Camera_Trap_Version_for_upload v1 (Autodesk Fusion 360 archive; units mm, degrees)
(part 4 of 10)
sketch "Sketch1" plane through (-17, 0, 0) normal (-1, 0, 0) x axis (0, -1, 0)
  line L1 (0, 133.1) -> (0, 122)
  line L2 (0, 70.6) -> (0, 133.1)
  line L3 (0, 143.2) -> (0, 154.3)
  line L4 (0, 143.2) -> (0, 205)
  line L5 (10, 225) -> (-10, 225)
  line L6 (20, 60) -> (20, 215)
  line L7 (-20, 50) -> (10, 50)
  line L8 (-20, 215) -> (-20, 50)
  line L9 (12.5837, 115) -> (-10, 115)
  line L10 (12.5837, 90.729) -> (12.5837, 115)
  line L11 (-10, 90.729) -> (12.5837, 90.729)
  line L12 (-10, 115) -> (-10, 90.729)
  line L13 (10, 185) -> (-10, 185)
  line L14 (10, 160) -> (10, 185)
  line L15 (-10, 160) -> (10, 160)
  line L16 (-10, 185) -> (-10, 160)
  circle C1 centre (0, 70.6) radius 13.1
  circle C2 centre (0, 70.6) radius 11.1
  circle C3 centre (0, 133.1) radius 11.1
  circle C4 centre (0, 143.2) radius 11.1
  arc A1 centre (-10, 215) radius 10 clockwise from (-20, 215) to (-10, 225)
  arc A2 centre (10, 215) radius 10 clockwise from (10, 225) to (20, 215)
  arc A3 centre (10, 60) radius 10 clockwise from (20, 60) to (10, 50)
  point P5 (0, 133.1)
  point P6 (0, 133.1)
  point P7 (0, 133.1)
  point P3 (0, 70.6)
  point P8 (0, 70.6)
  point P10 (0, 143.2)
  point P11 (0, 143.2)
  point P13 (0, 143.2)
  point P4 (0, 122)
  point P9 (0, 154.3)
  concentric C1 C2
  vertical L1
  coincident P5 P6
  coincident P6 P7
  coincident P3 P8
  parallel L1 L2
  vertical L3
  coincident P10 P11
  coincident P11 P13
  parallel L3 L4
  horizontal L5
  vertical L6
  horizontal L7
  vertical L8
  horizontal L9
  vertical L10
  horizontal L11
  vertical L12
  horizontal L13
  vertical L14
  horizontal L15
  vertical L16
  tangent L8 A1
  tangent L5 A1
  tangent L5 A2
  tangent L6 A2
  equal A1 A2
  tangent L6 A3
  tangent L7 A3
  equal A1 A3
  dimension "d792" diameter C2 = 22.2
  dimension "d793" distance P4 P5 = 11.1
  dimension "d794" diameter C3 = 22.2
  dimension "d796" distance P9 P10 = 11.1
  dimension "d797" diameter C4 = 22.2
  dimension "d798" radius A1 = 10
extrude "Extrude1" new body sketch "Sketch1" profile of C1 L5 L6 L7 L8 L9 L10 L11 L12 L13 L14 L15 L16 A1 A2 A3 against normal blind 5
combine "Combine1"
extrude "Extrude8" new body sketch "Sketch1" profile of L6 L7 L10 L11 L21 L22 L24 L25 L26 L27 against normal blind 149 and along normal blind 7 bodies "Back_wall"
sketch "Sketch2" plane through (0, 0, 100) normal (0, 0, 1) x axis (-1, 0, 0)
  line L1 (-136, 15) -> (-136, -15)
  line L2 (-139, 15) -> (-136, 15)
  line L3 (-139, -15) -> (-139, 15)
  line L4 (-136, -15) -> (-139, -15)
combine "Combine3"
copy_paste_bodies "CopyPasteBodies2"
move "Move2"
extrude "Extrude7" add of existing geometry blind 1
extrude "Extrude8" new body of existing geometry blind 12
extrude "Extrude9" new body of existing geometry blind 10
extrude "Extrude10" new body of existing geometry blind 52.5
extrude "Extrude11" new body of existing geometry blind 51
sketch "Sketch4" plane through (0, 0, 180.1585) normal (0, 0, 1) x axis (-1, 0, 0)
  line L1 (-39.225, -41) -> (-39.225, -35)
  line L2 (11.775, -41) -> (-39.225, -41)
  line L3 (11.775, -35) -> (11.775, -41)
  line L4 (-39.225, -35) -> (11.775, -35)
  line L5 (1.775, -41) -> (11.775, -41)
  line L6 (1.775, -31) -> (1.775, -41)
  line L7 (11.775, -31) -> (1.775, -31)
  line L8 (11.775, -41) -> (11.775, -31)
  point P4 (11.775, -41)
  point P6 (11.775, -41)
  point P7 (1.775, -41)
  point P9 (11.775, -31)
  horizontal L5
  vertical L6
  horizontal L7
  vertical L8
  coincident P4 P6
  dimension "d822" distance P6 P7 = 10
  dimension "d823" distance P6 P9 = 10
extrude "Extrude12" new body sketch "Sketch4" profile of L2 L3 L4 L5 L6 L8 along normal blind 30
sketch "Sketch5" plane through (-20.1975, 0, 0) normal (-1, 0, 0) x axis (0, -1, 0)
  line L1 (-52.3693, 30.245) -> (-52.3693, 255.1758)
  line L2 (-32.3693, 30.245) -> (-52.3693, 30.245)
  line L3 (-2.1894, 30.245) -> (-32.3693, 30.245)
  curve K1 (36.0257, 253.4503) -> (39.9781, 236.096)
  line L4 (3.2602, 255.1758) -> (36.0257, 253.4503)
  line L5 (-52.3693, 255.1758) -> (-1.9988, 255.1758)
  line L6 (-42, 182.1437) -> (-42, 210)
  arc A1 centre (-2.1894, 80.245) radius 50 clockwise from (40.2825, 106.6295) to (-2.1894, 30.245)
  arc A2 centre (82.7543, 133.0139) radius 50 clockwise from (40.2825, 106.6295) to (32.7706, 134.2915)
  arc A3 centre (2.3992, 135.0677) radius 30.3814 clockwise from (32.4457, 139.5658) to (32.7706, 134.2915)
  arc A4 centre (81.8947, 146.9684) radius 50 clockwise from (32.4457, 139.5658) to (41.2627, 176.1067)
  arc A5 centre (0.6307, 205.245) radius 50 clockwise from (39.9781, 236.096) to (41.2627, 176.1067)
  arc A6 centre (0.6307, 205.245) radius 50 clockwise from (-1.9988, 255.1758) to (3.2602, 255.1758)
  vertical L6
sketch "Sketch6" plane through (0, 35, 0) normal (0, -1, 0) x axis (1, 0, 0)
  line L1 (-1.775, 180.1585) -> (-11.775, 180.1585)
  line L2 (-1.775, 210.1585) -> (-1.775, 180.1585)
  line L3 (-11.775, 210.1585) -> (-1.775, 210.1585)
  line L4 (-11.775, 180.1585) -> (-11.775, 210.1585)
  line L5 (-20.2, 195.1585) -> (-11.775, 195.1585)
  line L6 (-11.775, 205) -> (-20.2, 205)
  line L7 (-11.775, 195.1585) -> (-11.775, 205)
  line L8 (-26, 205) -> (-20.2, 205)
  line L9 (-26, 195.1585) -> (-20.2, 195.1585)
  line L10 (-26, 205) -> (-26, 195.1585)
  point P6 (-11.775, 195.1585)
  horizontal L5
  horizontal L6
  vertical L7
  midpoint L4 P6
  parallel L6 L8
  parallel L5 L9
  perpendicular L8 L10
extrude "Extrude13" new body sketch "Sketch6" profile of L4 L5 L6 L7 against normal blind 6
sketch "Sketch7" plane through (0, 52.3693, 0) normal (0, -1, 0) x axis (1, 0, 0)
  line L1 (135.8025, 30.245) -> (-20.1975, 30.245)
  line L2 (135.8025, 292.8982) -> (135.8025, 30.245)
  line L3 (-20.1975, 292.8982) -> (135.8025, 292.8982)
  line L4 (-20.1975, 30.245) -> (-20.1975, 292.8982)
  line L5 (8.4868, 210) -> (0, 210)
  line L6 (8.4868, 184.467) -> (8.4868, 210)
  line L7 (0, 184.467) -> (8.4868, 184.467)
  line L8 (0, 210) -> (0, 184.467)
  line L9 (4.2434, 184.467) -> (4.2434, 210)
  circle C1 centre (4.2434, 204.9529) radius 1.5
  circle C2 centre (4.2434, 190.0169) radius 1.5
  point P10 (4.2434, 210)
  point P11 (4.2434, 184.467)
  point P12 (4.2434, 204.9529)
  point P13 (4.2434, 190.0169)
  horizontal L5
  vertical L6
  horizontal L7
  vertical L8
  midpoint L5 P10
  midpoint L7 P11
  coincident L9 P12
  coincident L9 P13
  dimension "d830" diameter C1 = 3
  dimension "d831" diameter C2 = 3
extrude "Extrude15" new body sketch "Sketch7" profile of L5 L6 L7 L8 C1 C2 along normal blind 25
sketch "Sketch8" plane through (0, 0, 0) normal (-1, 0, 0) x axis (0, -1, 0)
  line L1 (-52.3693, 184.467) -> (-52.3693, 210)
  line L2 (-27.3693, 184.467) -> (-52.3693, 184.467)
  line L3 (-27.3693, 210) -> (-27.3693, 184.467)
  line L4 (-52.3693, 210) -> (-27.3693, 210)
  line L5 (-27.3693, 210) -> (-33, 210)
  line L6 (-27.3693, 184.467) -> (-27.3693, 210)
  line L7 (-33, 184.467) -> (-27.3693, 184.467)
  line L8 (-33, 210) -> (-33, 184.467)
  point P4 (-27.3693, 184.467)
  point P8 (-27.3693, 184.467)
  point P6 (-33, 210)
  horizontal L5
  vertical L6
  horizontal L7
  vertical L8
  coincident P4 P8
  coincident L4 P6
sketch "Sketch9" plane through (0, 0, 0) normal (-1, 0, 0) x axis (0, -1, 0)
  line L1 (-52.3693, 184.467) -> (-52.3693, 210)
  line L2 (-27.3693, 184.467) -> (-52.3693, 184.467)
  line L3 (-27.3693, 210) -> (-27.3693, 184.467)
  line L4 (-52.3693, 210) -> (-27.3693, 210)
extrude "Extrude16" add sketch "Sketch8" profile of L2 L3 L4 L5 L6 L7 L8 along normal blind 14
sketch "Sketch4" plane through (-17, 0, 0) normal (1, 0, 0) x axis (0, 1, 0)
  line L1 (53, 254.9308) -> (53, 30)
  line L2 (2.6295, 254.9308) -> (53, 254.9308)
  line L3 (-35.395, 253.2053) -> (-2.6295, 254.9308)
  curve K1 (-35.395, 253.2053) -> (-39.3474, 235.851)
  line L4 (33, 30) -> (2.8201, 30)
  line L5 (53, 30) -> (33, 30)
  line L6 (53, 210) -> (43, 210)
  line L7 (53, 185) -> (53, 210)
  line L8 (43, 185) -> (53, 185)
  line L9 (43, 210) -> (43, 185)
  line L10 (48, 185) -> (43, 185)
  line L11 (48, 210) -> (48, 185)
  line L12 (43, 210) -> (48, 210)
  line L13 (43, 185) -> (43, 210)
  arc A1 centre (0, 205) radius 50 clockwise from (-2.6295, 254.9308) to (2.6295, 254.9308)
  arc A2 centre (0, 205) radius 50 clockwise from (-40.632, 175.8617) to (-39.3474, 235.851)
  arc A3 centre (-81.264, 146.7234) radius 50 clockwise from (-40.632, 175.8617) to (-31.815, 139.3208)
  arc A4 centre (-1.7685, 134.8228) radius 30.3814 clockwise from (-32.1399, 134.0465) to (-31.815, 139.3208)
  arc A5 centre (-82.1236, 132.769) radius 50 clockwise from (-32.1399, 134.0465) to (-39.6517, 106.3845)
  arc A6 centre (2.8201, 80) radius 50 clockwise from (2.8201, 30) to (-39.6517, 106.3845)
  circle C1 centre (51, 205) radius 1.5
  point P21 (53, 185)
  point P25 (48, 210)
  horizontal L6
  vertical L7
  horizontal L8
  vertical L9
  coincident L1 P21
  horizontal L10
  vertical L11
  horizontal L12
  vertical L13
  midpoint L6 P25
  dimension "d836" diameter C1 = 3
extrude "Extrude9" new body sketch "Sketch4" profile of L1 L6 L7 L8 C1 L11 along normal blind 5
extrude "Extrude10" new body sketch "Sketch4" profile of L6 L8 L9 L10 L11 L12 L13 along normal blind 17
sketch "Sketch5" plane through (0, 43, 0) normal (0, -1, 0) x axis (1, 0, 0)
  line L1 (0, 185) -> (-17, 185)
  line L2 (0, 210) -> (0, 185)
  line L3 (-17, 210) -> (0, 210)
  line L4 (0, 210) -> (-5, 210)
  line L5 (0, 185) -> (0, 210)
  line L6 (-5, 185) -> (0, 185)
  line L7 (-5, 210) -> (-5, 185)
  line L8 (-17, 185) -> (-17, 210)
  point P4 (0, 185)
  point P8 (0, 185)
  point P6 (-5, 210)
  horizontal L4
  vertical L5
  horizontal L6
  vertical L7
  coincident P4 P8
  coincident L3 P6
extrude "Extrude11" add sketch "Sketch5" profile of L1 L2 L3 L4 L5 L6 L7 along normal blind 7
sketch "Sketch7" plane through (-24, 0, 0) normal (-1, 0, 0) x axis (0, -1, 0)
  line L1 (-53, 30) -> (-53, 254.9308)
  line L2 (-33, 30) -> (-53, 30)
  line L3 (-2.8201, 30) -> (-33, 30)
  curve K1 (35.395, 253.2053) -> (39.3474, 235.851)
  line L4 (2.6295, 254.9308) -> (35.395, 253.2053)
  line L5 (-53, 254.9308) -> (-2.6295, 254.9308)
  line L6 (-35, 194) -> (-42, 194)
  line L7 (-35, 205) -> (-35, 194)
  line L8 (-35, 213) -> (-35, 205)
  line L9 (-42, 213) -> (-42, 194)
  line L10 (-35, 213) -> (-42, 213)
  arc A1 centre (-2.8201, 80) radius 50 clockwise from (39.6517, 106.3845) to (-2.8201, 30)
  arc A2 centre (82.1236, 132.769) radius 50 clockwise from (39.6517, 106.3845) to (32.1399, 134.0465)
  arc A3 centre (1.7685, 134.8228) radius 30.3814 clockwise from (31.815, 139.3208) to (32.1399, 134.0465)
  arc A4 centre (81.264, 146.7234) radius 50 clockwise from (31.815, 139.3208) to (40.632, 175.8617)
  arc A5 centre (0, 205) radius 50 clockwise from (39.3474, 235.851) to (40.632, 175.8617)
  arc A6 centre (0, 205) radius 50 clockwise from (-2.6295, 254.9308) to (2.6295, 254.9308)
  point P21 (-35, 205)
  point P22 (-35, 213)
  horizontal L6
  perpendicular L6 L7
  perpendicular L6 L8
  perpendicular L6 L9
  dimension "d844" distance P21 P22 = 8
extrude "Extrude13" cut sketch "Sketch7" profile of L6 L7 L8 L9 L10 against normal blind 7
extrude "Extrude14" cut of existing geometry blind -6
extrude "Extrude15" cut of existing geometry blind -4
combine "Combine3"
fillet "Fillet2" radius 10
combine "Combine4"
extrude "Extrude18" add of existing geometry blind 12
fillet "Fillet3" radius 10
fillet "Fillet5" radius 5
fillet "Fillet6" radius 10
fillet "Fillet7" radius 5
fillet "Fillet9" radius 5
fillet "Fillet11" radius 1
extrude "Extrude16" new body sketch "Sketch1" profile of L19 L33 L34 L35 L36 A7 A8 A9 A10 against normal blind 10 bodies "OLD_LL_Tensor_holders"
extrude "Extrude17" new body sketch "Sketch1" profile of L14 L28 L29 L30 L31 A3 A4 A5 A6 against normal blind 10 bodies "OLD_LU_Tensor_holders (1)"
move "Move3"
move "Move4"
sketch "Sketch8" plane through (0, -44, 0) normal (0, -1, 0) x axis (1, 0, 0)
  line L1 (-17, 183) -> (-17, 197)
  line L2 (-7, 183) -> (-17, 183)
  line L3 (-7, 197) -> (-7, 183)
  line L4 (-17, 197) -> (-7, 197)
  line L5 (-12, 193) -> (-17, 193)
  line L6 (-12, 185) -> (-12, 193)
  line L7 (-17, 185) -> (-12, 185)
  line L8 (-17, 193) -> (-17, 185)
  point P6 (-17, 193)
  point P7 (-12, 193)
  point P9 (-17, 185)
  horizontal L5
  vertical L6
  horizontal L7
  vertical L8
  coincident L1 P6
  dimension "d895" distance P6 P7 = 5
  dimension "d896" distance P6 P9 = 8
extrude "Extrude18" cut sketch "Sketch8" profile of L1 L5 L6 L7 L8 against normal blind 10
sketch "Sketch9" plane through (0, -44, 0) normal (0, -1, 0) x axis (1, 0, 0)
  line L1 (-17, 63) -> (-17, 77)
  line L2 (-7, 63) -> (-17, 63)
  line L3 (-7, 77) -> (-7, 63)
  line L4 (-17, 77) -> (-7, 77)
  line L5 (-17, 77) -> (-17, 77)
  line L6 (-17, 73) -> (-17, 77)
  line L7 (-17, 73) -> (-17, 73)
  line L8 (-17, 77) -> (-17, 73)
  line L9 (-12, 73) -> (-17, 73)
  line L10 (-12, 65) -> (-12, 73)
  line L11 (-17, 65) -> (-12, 65)
  line L12 (-17, 73) -> (-17, 65)
  point P8 (-17, 73)
  point P2 (-17, 77)
  point P6 (-17, 77)
  point P10 (-12, 73)
  point P12 (-17, 65)
  vertical L6
  vertical L8
  coincident L1 P8
  coincident P2 P6
  horizontal L9
  vertical L10
  horizontal L11
  vertical L12
  dimension "d899" distance P8 P10 = 5
  dimension "d900" distance P8 P12 = 8
extrude "Extrude19" cut sketch "Sketch9" profile of L1 L9 L10 L11 L12 against normal blind 10
copy_paste_bodies "CopyPasteBodies3"
copy_paste_bodies "CopyPasteBodies4"
mirror "Mirror1" mirrorStitchTolerance 0.1 bodies "RL_Tensor_holders (1) (1) (1)"
move "Move7"
mirror "Mirror2" mirrorStitchTolerance 0.1 bodies "RU_Tensor_holders (1) (2)"
move "Move8"
sketch "Sketch1" plane through (-13.1975, 0, 0) normal (1, 0, 0) x axis (0, 1, 0)
  line L1 (34.3693, 213.245) -> (34.3693, 194.245)
  line L2 (41.3693, 213.245) -> (34.3693, 213.245)
  line L3 (41.3693, 194.245) -> (41.3693, 213.245)
  line L4 (34.3693, 194.245) -> (41.3693, 194.245)
  line L5 (52.3693, 255.1758) -> (52.3693, 30.245)
  line L6 (1.9988, 255.1758) -> (52.3693, 255.1758)
  line L7 (-36.0257, 253.4503) -> (-3.2602, 255.1758)
  curve K1 (-36.0257, 253.4503) -> (-39.9781, 236.096)
  line L8 (32.3693, 30.245) -> (2.1894, 30.245)
  line L9 (52.3693, 30.245) -> (32.3693, 30.245)
  line L10 (-39.63, 186.745) -> (-39.63, 186.845)
  line L11 (-42.13, 194.645) -> (-42.13, 194.745)
  line L12 (-44.63, 186.845) -> (-44.63, 195.225)
  line L13 (-44.6307, 185.245) -> (-44.6307, 193.245)
  line L14 (-44.6307, 193.245) -> (-44.6307, 197.245)
  line L15 (-41.6307, 200.245) -> (-32.6307, 200.245)
  line L16 (-29.6307, 197.245) -> (-29.6307, 183.245)
  line L17 (-32.6307, 180.245) -> (-41.6307, 180.245)
  line L18 (-44.6307, 183.245) -> (-44.6307, 185.245)
  line L19 (-39.6307, 193.245) -> (-44.6307, 193.245)
  line L20 (-39.6307, 189.245) -> (-39.6307, 193.245)
  line L21 (-34.6307, 185.345) -> (-44.6307, 185.345)
  line L22 (-34.6307, 193.145) -> (-34.6307, 185.345)
  line L23 (-44.6307, 193.145) -> (-34.6307, 193.145)
  line L24 (-44.6307, 185.345) -> (-44.6307, 193.145)
  line L25 (-34.6307, 193.145) -> (-44.6307, 185.345)
  line L26 (-44.6307, 193.145) -> (-34.6307, 185.345)
  line L27 (-44.6307, 197.245) -> (-44.6307, 193.245)
  line L28 (-44.6307, 195.245) -> (-44.6307, 193.245)
  line L29 (-59.6307, 189.245) -> (-39.6307, 189.245)
  line L30 (-44.6307, 183.245) -> (-44.6307, 185.245)
  line L31 (-44.6307, 195.245) -> (-44.6307, 193.245)
  line L32 (-44.6307, 185.245) -> (-44.6307, 183.245)
  line L33 (-44.6307, 195.245) -> (-44.6307, 193.245)
  line L34 (-52.596, 200.2959) -> (-44.63, 195.225)
  line L35 (-52.596, 178.1941) -> (-44.63, 183.265)
  arc A1 centre (-0.6307, 205.245) radius 50 clockwise from (-3.2602, 255.1758) to (1.9988, 255.1758)
  arc A2 centre (-81.8947, 146.9684) radius 50 clockwise from (-41.2627, 176.1067) to (-32.4457, 139.5658)
  arc A3 centre (-2.3992, 135.0677) radius 30.3814 clockwise from (-32.7706, 134.2915) to (-32.4457, 139.5658)
  arc A4 centre (-82.7543, 133.0139) radius 50 clockwise from (-32.7706, 134.2915) to (-40.2825, 106.6295)
  arc A5 centre (2.1894, 80.245) radius 50 clockwise from (2.1894, 30.245) to (-40.2825, 106.6295)
  arc A6 centre (-41.6307, 197.245) radius 3 clockwise from (-44.6307, 197.245) to (-41.6307, 200.245)
  arc A7 centre (-32.6307, 197.245) radius 3 clockwise from (-32.6307, 200.245) to (-29.6307, 197.245)
  arc A8 centre (-32.6307, 183.245) radius 3 clockwise from (-29.6307, 183.245) to (-32.6307, 180.245)
  arc A9 centre (-41.6307, 183.245) radius 3 clockwise from (-41.6307, 180.245) to (-44.6307, 183.245)
  circle C1 centre (-59.6307, 189.245) radius 13.1
  circle C2 centre (-59.6307, 189.245) radius 6.5
  circle C3 centre (-59.6307, 189.245) radius 11.1
  arc A10 centre (-0.6307, 205.245) radius 50 clockwise from (-41.2627, 176.1067) to (-39.9781, 236.096)
  point P29 (-44.6307, 193.245)
  point P44 (-44.6307, 193.245)
  point P51 (-39.6307, 189.245)
  point P46 (-39.6307, 189.245)
  point P31 (-44.6307, 197.245)
  point P52 (-44.6307, 197.245)
  point P53 (-44.6307, 195.245)
  point P54 (-39.6307, 189.245)
  point P55 (-59.6307, 189.245)
  point P56 (-59.6307, 189.245)
  point P30 (-44.6307, 185.245)
  point P57 (-44.6307, 185.245)
  point P41 (-44.6307, 183.245)
  point P58 (-44.6307, 183.245)
  point P59 (-44.6307, 193.245)
  point P60 (-44.6307, 183.245)
  point P61 (-44.6307, 185.245)
  point P62 (-44.6307, 193.245)
  point P63 (-52.596, 200.2959)
  point P28 (-44.63, 195.225)
  point P64 (-44.63, 183.265)
  point P65 (-52.596, 178.1941)
  point P45 (-39.6307, 193.245)
  point P49 (-34.6307, 193.145)
  point P50 (-44.6307, 193.145)
  point P48 (-34.6307, 185.345)
  coincident P29 P44
  perpendicular L12 L19
  perpendicular L19 L20
  horizontal L21
  perpendicular L21 L22
  parallel L21 L23
  parallel L22 L24
  coincident L25 P51
  coincident L26 P51
  coincident P46 P51
  coincident P31 P52
  midpoint L14 P53
  perpendicular L19 L28
  coincident P51 P54
  perpendicular L20 L29
  coincident P55 P56
  coincident P30 P57
  coincident P41 P58
  coincident P29 P59
  coincident P41 P60
  coincident P30 P61
  coincident P29 P62
  coincident C1 P63
  tangent C1 L34
  symmetric P28 L29 P64
  symmetric L29 P63 P65
  concentric C1 C2
  concentric C2 C3
  dimension "d913" distance P44 P45 = 5
  dimension "d914" distance P45 P46 = 4
  dimension "d915" distance P49 P50 = 10
  dimension "d916" distance P48 P49 = 7.8
  dimension "d922" distance P54 P55 = 20
  dimension "d923" diameter C1 = 26.2
  dimension "d924" diameter C2 = 13
  dimension "d925" diameter C3 = 22.2
extrude "Extrude1" new body sketch "Sketch1" profile of L12 L13 L14 L18 L21 L22 L23 L24 L27 L28 L29 C1 L30 L31 L32 L33 L34 L35 C2 C3 along normal blind 5 bodies "LU_tensor_cap_or"
extrude "Extrude4" add sketch "Sketch1" profile of L13 L14 L18 L24 L27 L28 L29 C1 L30 L31 L32 L33 L34 L35 C2 C3 blind 2 from offset 5
extrude "Extrude5" cut sketch "Sketch1" profile of C2 blind -2 from offset 7
extrude "Extrude6" add sketch "Sketch1" profile of L29 C1 C3 blind 7 from offset 7
sketch "Sketch2" plane through (-13.1975, 0, 0) normal (1, 0, 0) x axis (0, 1, 0)
  line L1 (34.3693, 213.245) -> (34.3693, 194.245)
  line L2 (41.3693, 213.245) -> (34.3693, 213.245)
  line L3 (41.3693, 194.245) -> (41.3693, 213.245)
  line L4 (34.3693, 194.245) -> (41.3693, 194.245)
  line L5 (52.3693, 255.1758) -> (52.3693, 30.245)
  line L6 (1.9988, 255.1758) -> (52.3693, 255.1758)
  line L7 (-36.0257, 253.4503) -> (-3.2602, 255.1758)
  curve K1 (-36.0257, 253.4503) -> (-39.9781, 236.096)
  line L8 (32.3693, 30.245) -> (2.1894, 30.245)
  line L9 (52.3693, 30.245) -> (32.3693, 30.245)
  arc A1 centre (-0.6307, 205.245) radius 50 clockwise from (-3.2602, 255.1758) to (1.9988, 255.1758)
  arc A2 centre (-81.8947, 146.9684) radius 50 clockwise from (-41.2627, 176.1067) to (-32.4457, 139.5658)
  arc A3 centre (-2.3992, 135.0677) radius 30.3814 clockwise from (-32.7706, 134.2915) to (-32.4457, 139.5658)
  arc A4 centre (-82.7543, 133.0139) radius 50 clockwise from (-32.7706, 134.2915) to (-40.2825, 106.6295)
  arc A5 centre (2.1894, 80.245) radius 50 clockwise from (2.1894, 30.245) to (-40.2825, 106.6295)
  arc A6 centre (-0.6307, 205.245) radius 50 clockwise from (-41.2627, 176.1067) to (-39.9781, 236.096)
sketch "Small_bearings_L" plane through (-17, 0.6307, -0.245) normal (1, 0, 0) x axis (0, 1, 0)
  circle C1 centre (-39.1086, 196.6236) radius 5.1
  circle C2 centre (-39.1086, 196.6236) radius 7
  circle C3 centre (-39.1086, 196.6236) radius 2.5
  circle C4 centre (-39.1086, 86.6236) radius 7
  circle C5 centre (-39.1086, 86.6236) radius 5.1
  circle C6 centre (-39.1086, 86.6236) radius 2.5
  circle C7 centre (-39.1086, 196.6236) radius 7
  circle C8 centre (-39.1086, 196.6236) radius 5.1
  circle C9 centre (-39.1086, 196.6236) radius 2.5
  concentric C1 C3
  concentric C5 C6
  concentric C8 C9
  dimension "d945" diameter C1 = 10.2
  dimension "d947" diameter C2 = 14
  dimension "d953" diameter C3 = 5
  dimension "d954" diameter C5 = 10.2
  dimension "d955" diameter C4 = 14
  dimension "d956" diameter C6 = 5
  dimension "d957" diameter C8 = 10.2
  dimension "d958" diameter C7 = 14
  dimension "d959" diameter C9 = 5
extrude "Extrude22" cut sketch "Small_bearings_L" profile of C1 C2 C3 C7 C8 C9 against normal blind 4
extrude "Extrude23" cut sketch "Small_bearings_L" profile of C4 C5 C6 against normal blind 4
sketch "Small_bearings_R" plane through (125, 0, 0) normal (-1, 0, 0) x axis (0, -1, 0)
  line L1 (-53, 30) -> (-53, 254.9308)
  line L2 (-33, 30) -> (-53, 30)
  line L3 (-2.8201, 30) -> (-33, 30)
  curve K1 (35.395, 253.2053) -> (39.3474, 235.851)
  line L4 (2.6295, 254.9308) -> (35.395, 253.2053)
  line L5 (-53, 254.9308) -> (-2.6295, 254.9308)
  arc A1 centre (-2.8201, 80) radius 50 clockwise from (39.6517, 106.3845) to (-2.8201, 30)
  arc A2 centre (82.1236, 132.769) radius 50 clockwise from (39.6517, 106.3845) to (32.1399, 134.0465)
  arc A3 centre (1.7685, 134.8228) radius 30.3814 clockwise from (31.815, 139.3208) to (32.1399, 134.0465)
  arc A4 centre (81.264, 146.7234) radius 50 clockwise from (31.815, 139.3208) to (40.632, 175.8617)
  arc A5 centre (0, 205) radius 50 clockwise from (39.3474, 235.851) to (40.632, 175.8617)
  arc A6 centre (0, 205) radius 50 clockwise from (-2.6295, 254.9308) to (2.6295, 254.9308)
  circle C1 centre (38.4779, 86.3786) radius 2.5
  circle C2 centre (38.4779, 86.3786) radius 5.1
  circle C3 centre (38.4779, 86.3786) radius 7
  circle C4 centre (38.4779, 196.3786) radius 7
  circle C5 centre (38.4779, 196.3786) radius 5.1
  circle C6 centre (38.4779, 196.3786) radius 2.5
  circle C7 centre (38.4779, 196.3786) radius 2.5
  circle C8 centre (38.4779, 196.3786) radius 5.1
  circle C9 centre (38.4779, 196.3786) radius 7
  circle C10 centre (38.4779, 86.3786) radius 2.5
  circle C11 centre (38.4779, 86.3786) radius 5.1
  circle C12 centre (38.4779, 86.3786) radius 7
  circle C13 centre (38.4779, 196.3786) radius 7
  circle C14 centre (38.4779, 196.3786) radius 5.1
  circle C15 centre (38.4779, 86.3786) radius 5.1
  circle C16 centre (38.4779, 86.3786) radius 7
  concentric C4 C7
  concentric C6 C8
  concentric C5 C9
  concentric C1 C10
  concentric C1 C11
  concentric C1 C12
  concentric C8 C13
  concentric C5 C14
  concentric C3 C15
  concentric C1 C16
  dimension "d966" diameter C7 = 5
  dimension "d967" diameter C8 = 10.2
  dimension "d968" diameter C9 = 14
  dimension "d969" diameter C10 = 5
  dimension "d970" diameter C11 = 10.2
  dimension "d971" diameter C12 = 14
extrude "Extrude24" new body sketch "Small_bearings_L" profile of C3 C9 along normal blind 142
extrude "Extrude25" new body sketch "Small_bearings_L" profile of C6 along normal blind 142 bodies "Lower_Tensor"
external_derived "ExternalDerived1"
move "Move2"
external_derived "ExternalDerived2" sketch "Sketch6"
derived_instance "DerivedInstance1"
external_derived "ExternalDerived3"
derived_instance "DerivedInstance2"
move "Move3"
move "Move4"
move "Move5"
move "Move6"
move_face "MoveFace1"
position "Position22"
sketch "Sketch1" plane through (0, 52.3693, 0) normal (0, -1, 0) x axis (1, 0, 0)
  line L1 (135.8025, 30.245) -> (-20.1975, 30.245)
  line L2 (135.8025, 255.1782) -> (135.8025, 30.245)
  line L3 (-20.1975, 255.1782) -> (135.8025, 255.1782)
  line L4 (-20.1975, 30.245) -> (-20.1975, 255.1782)
  line L5 (126, 230) -> (108, 230)
  line L6 (126, 200) -> (126, 230)
  line L7 (108, 200) -> (126, 200)
  line L8 (108, 230) -> (108, 200)
  point P6 (108, 230)
  point P7 (126, 230)
  point P9 (108, 200)
  horizontal L5
  vertical L6
  horizontal L7
  vertical L8
  dimension "d976" distance P6 P7 = 18
  dimension "d977" distance P6 P9 = 30
extrude "Extrude1" new body sketch "Sketch1" profile of L5 L6 L7 L8 along normal blind 5.4
move "Move1"
position "Position23"
sketch "Sketch12" plane through (0, 53, 0) normal (0, -1, 0) x axis (1, 0, 0)
  line L1 (132, 30) -> (-24, 30)
  line L2 (132, 254.9332) -> (132, 30)
  line L3 (-24, 254.9332) -> (132, 254.9332)
  line L4 (-24, 30) -> (-24, 254.9332)
  line L5 (120, 158) -> (66, 158)
  line L6 (120, 245) -> (120, 158)
  line L7 (66, 245) -> (120, 245)
  line L8 (66, 158) -> (66, 245)
  line L9 (123, 248) -> (123, 155)
  line L10 (63, 248) -> (123, 248)
  line L11 (63, 155) -> (63, 248)
  line L12 (123, 155) -> (63, 155)
  horizontal L5
  vertical L6
  horizontal L7
  vertical L8
  dimension "d980" = 3
extrude "Extrude26" new body sketch "Sketch12" profile of L5 L6 L7 L8 L9 L12 L10 L11 along normal blind 22 bodies "Halfbridge_holder"
sketch "Sketch13" plane through (125, 0, 0) normal (-1, 0, 0) x axis (0, -1, 0)
  line L1 (11.3693, 148.5581) -> (-24.3276, 148.5581)
  line L2 (11.3693, 123.5581) -> (-24.3276, 123.5581)
  line L3 (-33.7807, 138.4085) -> (-33.7807, 138.4081)
  line L4 (-33.7807, 138.4085) -> (-34.161, 138.0281)
  line L5 (-34.161, 145.088) -> (-33.7807, 144.7077)
  line L6 (-33.7807, 144.7081) -> (-33.7807, 144.7077)
  line L7 (-36.1659, 143.2798) -> (-36.1659, 143.2913)
  line L8 (-36.1659, 143.2913) -> (-34.2232, 143.2913)
  line L9 (-34.2, 143.2798) -> (-34.2232, 143.2913)
  line L10 (-36.661, 145.088) -> (-34.161, 145.088)
  curve K1 (-37.1562, 143.1166) -> (-37.1489, 143.0744)
  line L11 (-36.1659, 143.2798) -> (-34.2, 143.2798)
  line L12 (-36.1659, 139.8364) -> (-34.2, 139.8364)
  curve K2 (-37.1562, 144.5928) -> (-36.661, 145.088)
  line L13 (-37.1562, 143.1187) -> (-37.1562, 143.1166)
  line L14 (-36.1659, 139.8248) -> (-36.1659, 139.8364)
  line L15 (-36.1659, 139.8248) -> (-34.2232, 139.8248)
  line L16 (-34.2232, 139.8248) -> (-34.2, 139.8364)
  line L17 (-36.661, 138.0281) -> (-34.161, 138.0281)
  curve K3 (-37.1562, 143.0321) -> (-37.1489, 143.0744)
  curve K4 (-37.1489, 140.0417) -> (-37.1562, 140.084)
  line L18 (-24.3276, 123.5581) -> (-32.6307, 123.5581)
  line L19 (-24.3276, 148.5581) -> (-32.6307, 148.5581)
  line L20 (-33.6307, 147.5581) -> (-33.6307, 144.5581)
  line L21 (-33.6307, 133.5581) -> (-33.6307, 138.5581)
  line L22 (-33.6307, 127.5581) -> (-33.6307, 124.5581)
  line L23 (12.3693, 127.5581) -> (12.3693, 144.5581)
  line L24 (12.3693, 147.5581) -> (12.3693, 144.5581)
  line L25 (12.3693, 127.5581) -> (12.3693, 124.5581)
  line L26 (-37.1562, 139.9995) -> (-37.1562, 139.9974)
  curve K5 (-36.661, 138.0281) -> (-37.1562, 138.5233)
  line L27 (-33.7807, 127.5581) -> (-33.7807, 128.0581)
  line L28 (-33.7807, 133.0581) -> (-33.7807, 133.5581)
  line L29 (-36.6307, 128.0581) -> (-36.6307, 130.5581)
  line L30 (-36.6307, 130.5581) -> (-36.6307, 133.0581)
  line L31 (-33.7807, 144.7081) -> (-33.6307, 144.5581)
  line L32 (-33.7807, 138.4081) -> (-33.6307, 138.5581)
  line L33 (-37.1562, 143.1187) -> (-37.1562, 144.5928)
  line L34 (-37.1562, 140.084) -> (-37.1562, 143.0321)
  line L35 (-37.1562, 138.5233) -> (-37.1562, 139.9974)
  line L36 (-33.6307, 127.5581) -> (-33.7807, 127.5581)
  line L37 (-33.6307, 133.5581) -> (-33.7807, 133.5581)
  line L38 (-33.7807, 128.0581) -> (-36.6307, 128.0581)
  line L39 (-33.7807, 133.0581) -> (-36.6307, 133.0581)
  line L40 (10, 150) -> (-33, 150)
  line L41 (15, 127) -> (15, 145)
  line L42 (-33, 122) -> (10, 122)
  line L43 (-38, 145) -> (-38, 127)
  line L44 (-33, 119) -> (10, 119)
  line L45 (-41, 145) -> (-41, 127)
  line L46 (10, 153) -> (-33, 153)
  line L47 (18, 127) -> (18, 145)
  closed curve K6 centre (-36.6611, 139.9995)
  arc A1 centre (11.3693, 124.5581) radius 1 clockwise from (12.3693, 124.5581) to (11.3693, 123.5581)
  arc A2 centre (11.3693, 147.5581) radius 1 clockwise from (11.3693, 148.5581) to (12.3693, 147.5581)
  arc A3 centre (-32.6307, 147.5581) radius 1 clockwise from (-33.6307, 147.5581) to (-32.6307, 148.5581)
  arc A4 centre (-32.6307, 124.5581) radius 1 clockwise from (-32.6307, 123.5581) to (-33.6307, 124.5581)
  arc A5 centre (-33, 145) radius 5 clockwise from (-38, 145) to (-33, 150)
  arc A6 centre (-33, 127) radius 5 clockwise from (-33, 122) to (-38, 127)
  arc A7 centre (10, 145) radius 5 clockwise from (10, 150) to (15, 145)
  arc A8 centre (10, 127) radius 5 clockwise from (15, 127) to (10, 122)
  arc A9 centre (-33, 127) radius 8 clockwise from (-33, 119) to (-41, 127)
  arc A10 centre (-33, 145) radius 8 clockwise from (-41, 145) to (-33, 153)
  arc A11 centre (10, 145) radius 8 clockwise from (10, 153) to (18, 145)
  arc A12 centre (10, 127) radius 8 clockwise from (18, 127) to (10, 119)
  horizontal L40
  vertical L41
  horizontal L42
  vertical L43
  tangent L40 A5
  tangent L43 A5
  tangent L42 A6
  tangent L43 A6
  tangent L40 A7
  tangent L41 A7
  tangent L41 A8
  tangent L42 A8
  dimension "d983" = -3
  dimension "d1001" radius A5 = 5
  dimension "d1002" radius A6 = 5
  dimension "d1003" radius A7 = 5
  dimension "d1004" radius A8 = 5
extrude "Extrude27" new body sketch "Sketch13" along normal blind 20 bodies "Battery_Holder"
sketch "Sketch5" plane through (0, 0, 155.245) normal (0, 0, -1) x axis (1, 0, 0)
  line L1 (126.8025, -52.3693) -> (66.8025, -52.3693)
  line L2 (126.8025, -30.3693) -> (126.8025, -52.3693)
  line L3 (66.8025, -30.3693) -> (126.8025, -30.3693)
  line L4 (66.8025, -52.3693) -> (66.8025, -30.3693)
  line L5 (80.7045, -48.48) -> (80.7045, -47.6152)
  line L6 (80.7045, -48.48) -> (80.7045, -48.4985)
  line L7 (80.7045, -48.4985) -> (80.7045, -49.3818)
  line L8 (80.7045, -49.3818) -> (80.7045, -49.4003)
  line L9 (80.7045, -50.2652) -> (80.7045, -49.4003)
  line L10 (81.9357, -50.2652) -> (82.4132, -50.2652)
  line L11 (81.9357, -50.2652) -> (81.8745, -50.2652)
  line L12 (82.4132, -50.2652) -> (82.4745, -50.2652)
  line L13 (95.1745, -50.2652) -> (96.3445, -50.2652)
  line L14 (92.6345, -50.2652) -> (94.5745, -50.2652)
  line L15 (90.0945, -50.2652) -> (92.0345, -50.2652)
  line L16 (87.5545, -50.2652) -> (89.4945, -50.2652)
  line L17 (85.0145, -50.2652) -> (86.9545, -50.2652)
  line L18 (82.4745, -50.2652) -> (84.4145, -50.2652)
  line L19 (80.7045, -50.2652) -> (81.8745, -50.2652)
  line L20 (96.3445, -50.2652) -> (96.3445, -49.4003)
  line L21 (96.3445, -49.3818) -> (96.3445, -49.4003)
  line L22 (84.4757, -50.2652) -> (84.9532, -50.2652)
  line L23 (84.4757, -50.2652) -> (84.4145, -50.2652)
  line L24 (84.9532, -50.2652) -> (85.0145, -50.2652)
  line L25 (96.3445, -48.4985) -> (96.3445, -49.3818)
  line L26 (96.3445, -48.48) -> (96.3445, -48.4985)
  line L27 (80.7045, -47.6152) -> (96.3445, -47.6152)
  line L28 (96.3445, -48.48) -> (96.3445, -47.6152)
  line L29 (87.0157, -50.2652) -> (87.4932, -50.2652)
  line L30 (87.0157, -50.2652) -> (86.9545, -50.2652)
  line L31 (87.4932, -50.2652) -> (87.5545, -50.2652)
  line L32 (89.5557, -50.2652) -> (90.0332, -50.2652)
  line L33 (89.5557, -50.2652) -> (89.4945, -50.2652)
  line L34 (90.0332, -50.2652) -> (90.0945, -50.2652)
  line L35 (92.0957, -50.2652) -> (92.5732, -50.2652)
  line L36 (92.0957, -50.2652) -> (92.0345, -50.2652)
  line L37 (92.5732, -50.2652) -> (92.6345, -50.2652)
  line L38 (94.6357, -50.2652) -> (95.1132, -50.2652)
  line L39 (94.6357, -50.2652) -> (94.5745, -50.2652)
  line L40 (95.1132, -50.2652) -> (95.1745, -50.2652)
  line L41 (96.3445, -47.6152) -> (80.7045, -47.6152)
  line L42 (96.3445, -50.2652) -> (96.3445, -47.6152)
  line L43 (80.7045, -50.2652) -> (96.3445, -50.2652)
  line L44 (80.7045, -47.6152) -> (80.7045, -50.2652)
  point P16 (96.3445, -50.2652)
  point P44 (96.3445, -50.2652)
  point P6 (80.7045, -47.6152)
  point P42 (80.7045, -47.6152)
  horizontal L41
  vertical L42
  horizontal L43
  vertical L44
  coincident P16 P44
  coincident P6 P42
extrude "Extrude28" cut sketch "Sketch5" profile of L5 L6 L7 L8 L9 L10 L11 L12 L13 L14 L15 L16 L17 L18 L19 L20 L21 L22 L23 L24 L25 L26 L27 L28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 against normal blind 3
sketch "Sketch6" plane through (0, 0, 245.245) normal (0, 0, -1) x axis (1, 0, 0)
  line L1 (123.8025, -52.3693) -> (69.8025, -52.3693)
  line L2 (123.8025, -30.3693) -> (123.8025, -52.3693)
  line L3 (69.8025, -30.3693) -> (123.8025, -30.3693)
  line L4 (69.8025, -52.3693) -> (69.8025, -30.3693)
  line L5 (96.6045, -47.6152) -> (96.6045, -50.2652)
  line L6 (96.6045, -50.2652) -> (80.9645, -50.2652)
  line L7 (80.9645, -47.6152) -> (80.9645, -50.2652)
  line L8 (96.6045, -47.6152) -> (80.9645, -47.6152)
extrude "Extrude29" cut sketch "Sketch6" profile of L5 L6 L7 L8 against normal blind 6
sketch "Sketch14" plane through (0, 0, 245) normal (0, 0, -1) x axis (1, 0, 0)
  line L1 (92.802, -50.8959) -> (92.802, -48.2459)
  line L2 (77.162, -50.8959) -> (92.802, -50.8959)
  line L3 (77.162, -48.2459) -> (77.162, -50.8959)
  line L4 (92.802, -48.2459) -> (77.162, -48.2459)
  line L5 (120, -53) -> (66, -53)
  line L6 (120, -31) -> (120, -53)
  line L7 (66, -31) -> (120, -31)
  line L8 (66, -53) -> (66, -31)
  line L9 (102.1975, -47.6) -> (102.1975, -53)
  line L10 (120.1975, -53) -> (102.1975, -53)
  line L11 (102.1975, -47.6) -> (120.1975, -47.6)
  line L12 (120.1975, -47.6) -> (120.1975, -53)
  line L13 (112.1975, -47.6) -> (102.1975, -47.6)
  line L14 (112.1975, -53) -> (112.1975, -47.6)
  line L15 (102.1975, -53) -> (112.1975, -53)
  line L16 (102.1975, -47.6) -> (102.1975, -53)
  point P11 (102.1975, -47.6)
  point P14 (102.1975, -47.6)
  point P15 (112.1975, -47.6)
  horizontal L13
  vertical L14
  horizontal L15
  vertical L16
  coincident P11 P14
  dimension "d990" distance P14 P15 = 10
extrude "Extrude30" cut sketch "Sketch14" profile of L5 L6 L10 L11 L14 against normal blind 3
sketch "Sketch15" plane through (0, 0, 158) normal (0, 0, 1) x axis (-1, 0, 0)
  line L1 (-92.542, -48.2459) -> (-92.542, -50.8959)
  line L2 (-76.902, -48.2459) -> (-92.542, -48.2459)
  line L3 (-76.902, -50.8959) -> (-76.902, -48.2459)
  line L4 (-92.542, -50.8959) -> (-76.902, -50.8959)
  line L5 (-66, -53) -> (-120, -53)
  line L6 (-66, -31) -> (-66, -53)
  line L7 (-120, -31) -> (-66, -31)
  line L8 (-120, -53) -> (-120, -31)
  line L9 (-102.1975, -47.6) -> (-102.1975, -53)
  line L10 (-120.1975, -47.6) -> (-120.1975, -53)
  line L11 (-102.1975, -53) -> (-120.1975, -53)
  line L12 (-120.1975, -47.6) -> (-102.1975, -47.6)
  line L13 (-112.1975, -53) -> (-102.1975, -53)
  line L14 (-112.1975, -50) -> (-112.1975, -53)
  line L15 (-102.1975, -50) -> (-112.1975, -50)
  line L16 (-102.1975, -53) -> (-102.1975, -50)
  point P10 (-102.1975, -53)
  point P14 (-102.1975, -53)
  point P15 (-112.1975, -53)
  horizontal L13
  vertical L14
  horizontal L15
  vertical L16
  coincident P10 P14
  dimension "d993" distance P14 P15 = 10
extrude "Extrude31" cut sketch "Sketch15" profile of L5 L9 L11 L13 L14 L15 L16 against normal blind 3
position "Position24"
extrude "Extrude37" new body of existing geometry blind 7
sketch "Sketch18" plane through (132, 0, 0) normal (1, 0, 0) x axis (0, 1, 0)
  line L1 (-150.5352, 231.8021) -> (-151.5254, 235.0563)
  line L2 (-72.4247, 251.2552) -> (-148.3404, 230.5893)
  line L3 (-2.6295, 254.9308) -> (-72.4247, 251.2552)
  line L4 (53, 254.9308) -> (2.6295, 254.9308)
  line L5 (53, 292.6532) -> (53, 254.9308)
  line L6 (-150.2762, 237.3171) -> (53, 292.6532)
  arc A1 centre (-149.8034, 235.5803) radius 1.8 clockwise from (-151.5254, 235.0563) to (-150.2762, 237.3171)
  arc A2 centre (-148.8131, 232.3261) radius 1.8 clockwise from (-148.3404, 230.5893) to (-150.5352, 231.8021)
  arc A3 centre (0, 205) radius 50 clockwise from (-2.6295, 254.9308) to (2.6295, 254.9308)
  circle C1 centre (6.6916, 266.9657) radius 3.15
  dimension "d1016" diameter C1 = 6.3
extrude "Extrude38" cut sketch "Sketch18" + "Tests" profile of S2:C1 S2:C2 S1:C1 blind -13.3
sketch "Sketch19" plane through (132, 0, 0) normal (1, 0, 0) x axis (0, 1, 0)
  line L1 (-150.5352, 231.8021) -> (-151.5254, 235.0563)
  line L2 (-72.4247, 251.2552) -> (-148.3404, 230.5893)
  line L3 (-2.6295, 254.9308) -> (-72.4247, 251.2552)
  line L4 (53, 254.9308) -> (2.6295, 254.9308)
  line L5 (53, 292.6532) -> (53, 254.9308)
  line L6 (-150.2762, 237.3171) -> (53, 292.6532)
  circle C1 centre (6.6916, 266.9657) radius 3.15
  arc A1 centre (-149.8034, 235.5803) radius 1.8 clockwise from (-151.5254, 235.0563) to (-150.2762, 237.3171)
  arc A2 centre (-148.8131, 232.3261) radius 1.8 clockwise from (-148.3404, 230.5893) to (-150.5352, 231.8021)
  arc A3 centre (0, 205) radius 50 clockwise from (-2.6295, 254.9308) to (2.6295, 254.9308)
  circle C2 centre (6.6916, 266.9657) radius 6.3
  concentric C1 C2
  dimension "d1019" diameter C2 = 12.6
extrude "Extrude39" new body sketch "Sketch19" profile of C1 C2 along normal blind 37 bodies "Antennae"
sketch "Sketch20" plane through (169, 0, 0) normal (1, 0, 0) x axis (0, 1, 0)
  line L1 (11.1593, 266.9657) -> (2.0285, 266.9657)
  line L2 (16.1593, 394.9657) -> (16.1593, 271.9657)
  line L3 (2.0285, 399.9657) -> (11.1593, 399.9657)
  line L4 (-2.9715, 271.9657) -> (-2.9715, 394.9657)
  circle C1 centre (6.6916, 266.9657) radius 6.3
  arc A1 centre (2.0285, 394.9657) radius 5 clockwise from (-2.9715, 394.9657) to (2.0285, 399.9657)
  arc A2 centre (11.1593, 394.9657) radius 5 clockwise from (11.1593, 399.9657) to (16.1593, 394.9657)
  arc A3 centre (2.0285, 271.9657) radius 5 clockwise from (2.0285, 266.9657) to (-2.9715, 271.9657)
  arc A4 centre (11.1593, 271.9657) radius 5 clockwise from (16.1593, 271.9657) to (11.1593, 266.9657)
  point P4 (-2.9715, 399.9657)
  point P3 (-2.9715, 266.9657)
  perpendicular L1 L2
  parallel L1 L3
  parallel L2 L4
  horizontal L1
  coincident P4 L4
  coincident P4 L3
  tangent L4 A1
  tangent L3 A1
  tangent L3 A2
  tangent L2 A2
  equal A1 A2
  coincident P3 L4
  coincident P3 L1
  tangent L4 A3
  tangent L1 A3
  equal A1 A3
  tangent L2 A4
  tangent L1 A4
  equal A1 A4
  dimension "d1022" distance P3 P4 = 133
  dimension "d1023" radius A1 = 5
extrude "Extrude40" add sketch "Sketch20" profile of C1 L2 L3 L4 A1 A2 A3 A4 distance 3.3
extrude "Extrude41" add of existing geometry blind 3
external_derived "ExternalDerived4"
derived_instance "DerivedInstance3"
derived_instance "DerivedInstance1"
derived_instance "DerivedInstance2"
derived_instance "DerivedInstance3"
derived_instance "DerivedInstance4"
derived_instance "DerivedInstance1"
derived_instance "DerivedInstance2"
derived_instance "DerivedInstance1"
derived_instance "DerivedInstance2"
derived_instance "DerivedInstance3"
derived_instance "DerivedInstance4"
derived_instance "DerivedInstance5" sketch "Tests"
derived_instance "DerivedInstance6"
derived_instance "DerivedInstance7"
derived_instance "DerivedInstance1"
derived_instance "DerivedInstance2"
derived_instance "DerivedInstance3"
derived_instance "DerivedInstance4"
sketch "Projection_holders_and_buttons" plane through (-20.1975, 0, 0) normal (-1, 0, 0) x axis (0, -1, 0)
  line L1 (-34.3693, 194.245) -> (-34.3693, 213.245)
  line L2 (-41.3693, 194.245) -> (-34.3693, 194.245)
  line L3 (-41.3693, 213.245) -> (-41.3693, 194.245)
  line L4 (-34.3693, 213.245) -> (-41.3693, 213.245)
  line L5 (-52.3693, 30.245) -> (-52.3693, 255.1758)
  line L6 (-32.3693, 30.245) -> (-52.3693, 30.245)
  line L7 (-2.1894, 30.245) -> (-32.3693, 30.245)
  curve K1 (36.0257, 253.4503) -> (39.9781, 236.096)
  line L8 (3.2602, 255.1758) -> (36.0257, 253.4503)
  line L9 (-52.3693, 255.1758) -> (-1.9988, 255.1758)
  line L10 (-41, 210.1585) -> (-41, 190.1585)
  line L11 (-41, 190.1585) -> (-41, 180.1585)
  line L12 (-41, 180.1585) -> (-41, 175.1585)
  line L13 (-41, 175.1585) -> (-41, 110.9415)
  line L14 (-41, 110.9415) -> (-41, 105.9415)
  line L15 (-41, 105.9415) -> (-35, 105.9415)
  line L16 (-35, 105.9415) -> (-35, 110.9415)
  line L17 (-35, 175.1585) -> (-35, 110.9415)
  line L18 (-35, 180.1585) -> (-35, 190.1585)
  line L19 (-41, 210.1585) -> (-35, 210.1585)
  line L20 (-35, 210.1585) -> (-35, 190.1585)
  line L21 (-35, 175.1585) -> (-35, 180.1585)
  line L22 (12.6204, 133.0972) -> (12.6204, 143.0972)
  line L23 (-12.7796, 133.0972) -> (-12.7796, 143.0972)
  arc A1 centre (-2.1894, 80.245) radius 50 clockwise from (40.2825, 106.6295) to (-2.1894, 30.245)
  arc A2 centre (82.7543, 133.0139) radius 50 clockwise from (40.2825, 106.6295) to (32.7706, 134.2915)
  arc A3 centre (2.3992, 135.0677) radius 30.3814 clockwise from (32.4457, 139.5658) to (32.7706, 134.2915)
  arc A4 centre (81.8947, 146.9684) radius 50 clockwise from (32.4457, 139.5658) to (41.2627, 176.1067)
  arc A5 centre (0.6307, 205.245) radius 50 clockwise from (39.9781, 236.096) to (41.2627, 176.1067)
  arc A6 centre (0.6307, 205.245) radius 50 clockwise from (-1.9988, 255.1758) to (3.2602, 255.1758)
  circle C1 centre (-0.0736, 205.414) radius 13.1
  arc A7 centre (-0.0796, 133.0972) radius 12.7 clockwise from (12.6204, 133.0972) to (-12.7796, 133.0972)
  arc A8 centre (-0.0796, 143.0972) radius 12.7 clockwise from (-12.7796, 143.0972) to (12.6204, 143.0972)
combine "Combine1" bodies "Body1", "Body1 (1)", "Body1 (2)", "Body1 (3)", "Body1 (4)"
position "Position25"
extrude "Extrude42" cut of existing geometry blind -39.4479
fillet "Fillet12" radius 5
fillet "Fillet14" radius 2
fillet "Fillet15" radius 2.5
combine "Combine2" bodies "Body1 (1)", "Body1 (2)", "Body1 (3)", "Body1 (4)"
position "Position26"
sketch "Sketch21" plane through (-24, 0.6307, -0.245) normal (-1, 0, 0) x axis (0, -1, 0)
  line L1 (-18, 179.0417) -> (-45.508, 179.0417)
  line L2 (-15, 108) -> (-15, 176.0417)
  line L3 (-45.508, 105) -> (-18, 105)
  line L4 (-48.508, 176.0417) -> (-48.508, 108)
  line L5 (-19, 107.4076) -> (-19, 176.786)
  circle C1 centre (-19, 176.786) radius 1.4
  circle C2 centre (-45, 176.786) radius 1.4
  circle C3 centre (-45, 107.4) radius 1.4
  circle C4 centre (-19, 107.4) radius 1.4
  arc A1 centre (-45.508, 176.0417) radius 3 clockwise from (-48.508, 176.0417) to (-45.508, 179.0417)
  arc A2 centre (-18, 176.0417) radius 3 clockwise from (-18, 179.0417) to (-15, 176.0417)
  arc A3 centre (-45.508, 108) radius 3 clockwise from (-45.508, 105) to (-48.508, 108)
  arc A4 centre (-18, 108) radius 3 clockwise from (-15, 108) to (-18, 105)
  point P2 (-19, 176.786)
  point P6 (-19, 176.786)
  horizontal L1
  vertical L2
  horizontal L3
  vertical L4
  vertical L5
  coincident P2 P6
  tangent L4 A1
  tangent L1 A1
  tangent L1 A2
  tangent L2 A2
  tangent L4 A3
  tangent L3 A3
  tangent L2 A4
  tangent L3 A4
  dimension "d1047" diameter C1 = 2.8
  dimension "d1048" diameter C2 = 2.8
  dimension "d1049" diameter C3 = 2.8
  dimension "d1050" diameter C4 = 2.8
  dimension "d1053" radius A1 = 3
  dimension "d1054" radius A2 = 3
  dimension "d1055" radius A3 = 3
  dimension "d1056" radius A4 = 3
position "Position27"
extrude "Extrude43" cut sketch "Sketch21" profile of L1 L2 L3 L4 C1 C2 C3 C4 A1 A2 A3 A4 against normal blind 3
position "Position28"
extrude "Extrude45" cut sketch "Sketch21" profile of C1 C2 C3 C4 blind -3 from offset -3
sketch "Sketch22" plane through (0, 31, 0) normal (0, -1, 0) x axis (1, 0, 0)
  line L1 (66, 245) -> (66, 158)
  line L2 (120, 245) -> (66, 245)
  line L3 (120, 158) -> (120, 245)
  line L4 (66, 158) -> (120, 158)
  line L5 (123, 155) -> (63, 155)
  line L6 (123, 248) -> (123, 155)
  line L7 (63, 248) -> (123, 248)
  line L8 (63, 155) -> (63, 248)
  line L9 (72, 245) -> (66, 245)
  line L10 (72, 239) -> (72, 245)
  line L11 (66, 239) -> (72, 239)
  line L12 (66, 245) -> (66, 239)
  line L13 (114, 245) -> (120, 245)
  line L14 (114, 239) -> (114, 245)
  line L15 (120, 239) -> (114, 239)
  line L16 (120, 245) -> (120, 239)
  line L17 (72, 158) -> (66, 158)
  line L18 (72, 164) -> (72, 158)
  line L19 (66, 164) -> (72, 164)
  line L20 (66, 158) -> (66, 164)
  line L21 (114, 158) -> (120, 158)
  line L22 (114, 164) -> (114, 158)
  line L23 (120, 164) -> (114, 164)
  line L24 (120, 158) -> (120, 164)
  point P3 (66, 245)
  point P10 (66, 245)
  point P4 (120, 245)
  point P14 (120, 245)
  point P2 (66, 158)
  point P18 (66, 158)
  point P5 (120, 158)
  point P22 (120, 158)
  point P11 (72, 245)
  point P13 (66, 239)
  point P15 (114, 245)
  point P17 (120, 239)
  point P19 (72, 158)
  point P21 (66, 164)
  point P23 (114, 158)
  point P25 (120, 164)
  horizontal L9
  vertical L10
  horizontal L11
  vertical L12
  coincident P3 P10
  horizontal L13
  vertical L14
  horizontal L15
  vertical L16
  coincident P4 P14
  horizontal L17
  vertical L18
  horizontal L19
  vertical L20
  coincident P2 P18
  horizontal L21
  vertical L22
  horizontal L23
  vertical L24
  coincident P5 P22
  dimension "d1062" distance P10 P11 = 6
  dimension "d1063" distance P10 P13 = 6
  dimension "d1064" distance P14 P15 = 6
  dimension "d1065" distance P14 P17 = 6
  dimension "d1066" distance P18 P19 = 6
  dimension "d1067" distance P18 P21 = 6
  dimension "d1068" distance P22 P23 = 6
  dimension "d1069" distance P22 P25 = 6
extrude "Extrude46" add sketch "Sketch22" profile of L1 L2 L3 L4 L9 L10 L11 L12 L13 L14 L15 L16 L17 L18 L19 L20 L21 L22 L23 L24 blind -3 from offset -3
sketch "Sketch23" plane through (0, 53, 0) normal (0, -1, 0) x axis (1, 0, 0)
  line L1 (-24, 253.2053) -> (132, 253.2053)
  line L2 (-24, 30) -> (-24, 253.2053)
  line L3 (132, 30) -> (-24, 30)
  line L4 (132, 253.2053) -> (132, 30)
  circle C1 centre (33.7003, 229.3768) radius 1.4
  dimension "d1073" diameter C1 = 2.8
extrude "Extrude47" cut sketch "Sketch23" profile of C1 against normal blind 5
combine "Combine1"
combine "Combine1" bodies "Left_wall"
combine "Combine2"
sketch "Sketch1" plane through (-12, 0, 0) normal (1, 0, 0) x axis (0, 1, 0)
  line L1 (53, 185) -> (48, 185)
  line L2 (53, 210) -> (53, 185)
  line L3 (48, 210) -> (53, 210)
  line L4 (48, 195) -> (48, 210)
  line L5 (48, 185) -> (48, 195)
  circle C1 centre (51, 205) radius 1.5
extrude "Extrude1" cut sketch "Sketch1" profile of C1 against normal blind 10
sketch "Sketch24" plane through (0, 34, 0) normal (0, -1, 0) x axis (1, 0, 0)
  line L1 (72, 239) -> (66, 239)
  line L2 (72, 245) -> (72, 239)
  line L3 (66, 245) -> (72, 245)
  line L4 (66, 239) -> (66, 245)
  line L5 (93, 248) -> (63, 248)
  line L6 (93, 222) -> (93, 248)
  line L7 (93, 201.5) -> (93, 245)
  line L8 (120, 201.5) -> (93, 201.5)
  circle C1 centre (69, 242) radius 1.5
  circle C2 centre (117, 242) radius 1.5
  circle C3 centre (117, 161) radius 1.5
  circle C4 centre (69, 161) radius 1.5
  point P11 (93, 245)
  point P7 (63, 248)
  point P8 (93, 248)
  point P12 (93, 201.5)
  horizontal L5
  perpendicular L5 L6
  symmetric C1 L6 C2
  coincident L6 P11
  perpendicular L5 L7
  perpendicular L7 L8
  symmetric C2 L8 C3
  symmetric L6 C3 C4
  dimension "d1078" diameter C1 = 3
  dimension "d1079" distance P7 P8 = 30
  dimension "d1080" distance P11 P12 = 43.5
extrude "Extrude49" add of existing geometry blind 5
extrude "Extrude48" cut sketch "Sketch24" profile of C1 C2 C3 C4 against normal blind 2
extrude "Extrude50" cut of existing geometry blind -2
combine "Combine1" bodies "Back_wall", "Back_wall (1)"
